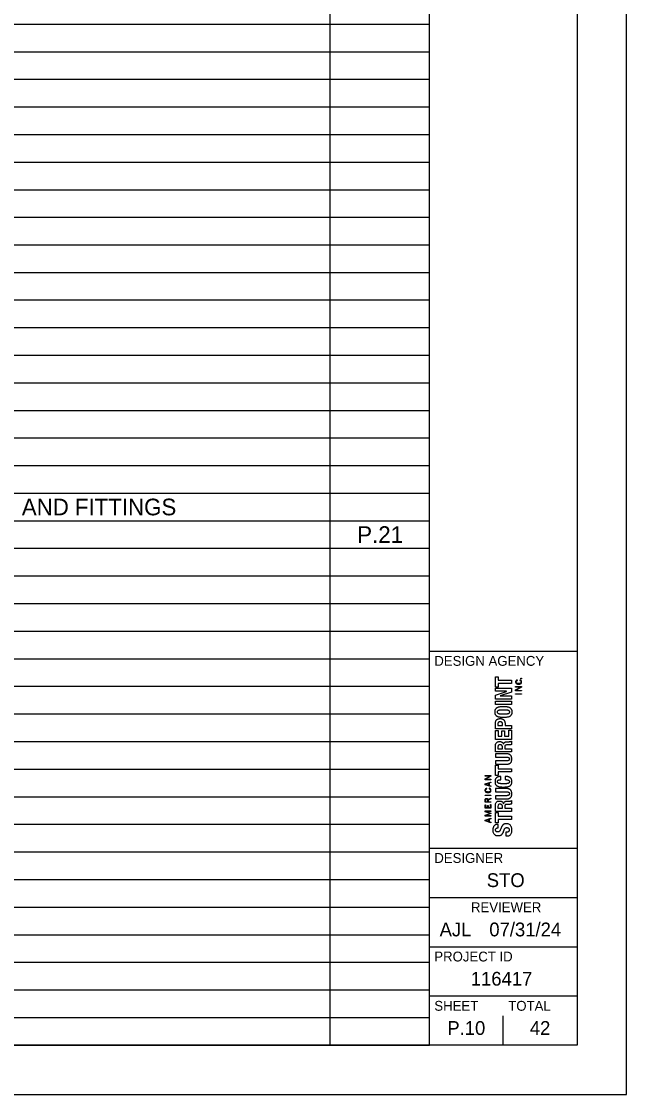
# Model space of a CAD drawing. Extents: x 0 to 34, y 0 to 22.
# Drawn here: x 27.86 to 34, y 0 to 10.89 of the extents above; entities that cross this region are included whole.
import ezdxf

# ---------------------------------------------------------------- set-up
doc = ezdxf.new("R2010")
doc.units = 0
for name, color, linetype in [('SH_Border', 7, 'Continuous'), ('SH_Cut_Line', 7, 'Continuous'), ('SH_Data', 7, 'Continuous')]:
    doc.layers.add(name, color=color, linetype=linetype)

msp = doc.modelspace()

# ---------------------------------------------------------------- linework, layer by layer
at = {"layer": 'SH_Border'}
for p, q in [((32, 0.5), (32, 21.5)), ((32, 4.5), (33.5, 4.5)), ((32, 2.5), (33.5, 2.5)), ((32, 2), (33.5, 2)), ((32, 1.5), (33.5, 1.5)), ((32, 1), (33.5, 1))]:
    msp.add_line(p, q, dxfattribs=at)
msp.add_lwpolyline([(1.5, 21.5), (33.5, 21.5), (33.5, 0.5), (1.5, 0.5)], close=True, dxfattribs=at)
at = {"layer": 'SH_Cut_Line'}
msp.add_lwpolyline([(0, 0), (34, 0), (34, 22), (0, 22)], close=True, dxfattribs=at)
at = {"layer": 'SH_Data'}
for p, q in [((30.995, 0.502), (30.995, 21.5)), ((32, 0.502), (32, 21.5)), ((1.5, 10.861), (32, 10.861)), ((1.5, 10.581), (32, 10.581)), ((1.5, 10.301), (32, 10.301)), ((1.5, 10.021), (32, 10.021)), ((1.5, 9.741), (32, 9.741)), ((1.5, 9.461), (32, 9.461)), ((1.5, 9.181), (32, 9.181)), ((1.5, 8.901), (32, 8.901)), ((1.5, 8.621), (32, 8.621)), ((1.5, 8.341), (32, 8.341)), ((1.5, 8.062), (32, 8.062)), ((1.5, 7.782), (32, 7.782)), ((1.5, 7.502), (32, 7.502)), ((1.5, 7.222), (32, 7.222)), ((1.5, 6.942), (32, 6.942)), ((1.5, 6.662), (32, 6.662)), ((1.5, 6.382), (32, 6.382)), ((1.5, 6.102), (32, 6.102)), ((1.5, 5.822), (32, 5.822)), ((1.5, 5.542), (32, 5.542)), ((1.5, 5.262), (32, 5.262)), ((1.5, 4.982), (32, 4.982)), ((1.5, 4.702), (32, 4.702)), ((1.5, 4.422), (32, 4.422)), ((1.5, 4.142), (32, 4.142)), ((1.5, 3.862), (32, 3.862)), ((1.5, 3.582), (32, 3.582)), ((32.75, 3.5), (32.75, 3.5)), ((32.75, 3.5), (32.75, 3.5)), ((1.5, 3.302), (32, 3.302)), ((1.5, 3.022), (32, 3.022)), ((1.5, 2.742), (32, 2.742)), ((1.5, 2.462), (32, 2.462)), ((1.5, 2.182), (32, 2.182)), ((1.5, 1.902), (32, 1.902)), ((1.5, 1.622), (32, 1.622)), ((1.5, 1.342), (32, 1.342)), ((1.5, 1.062), (32, 1.062)), ((1.5, 0.782), (32, 0.782)), ((32.75, 0.5), (32.75, 0.8)), ((32.375, 0.675), (32.375, 0.675)), ((1.5, 0.502), (32, 0.502))]:
    msp.add_line(p, q, dxfattribs=at)
for points in [[(32.67, 4.239), (32.697, 4.239), (32.697, 4.204), (32.833, 4.204), (32.833, 4.171), (32.697, 4.171), (32.697, 4.135), (32.67, 4.135), (32.67, 4.239)], [(32.875, 4.096), (32.875, 4.105), (32.925, 4.134), (32.925, 4.134), (32.875, 4.134), (32.875, 4.139), (32.935, 4.139), (32.935, 4.134), (32.88, 4.102), (32.88, 4.101), (32.935, 4.101), (32.935, 4.096), (32.875, 4.096)], [(32.935, 4.218), (32.927, 4.218), (32.927, 4.225), (32.935, 4.225), (32.935, 4.218)], [(32.67, 4.051), (32.781, 4.091), (32.781, 4.092), (32.67, 4.092), (32.67, 4.122), (32.833, 4.122), (32.833, 4.084), (32.719, 4.044), (32.719, 4.044), (32.833, 4.044), (32.833, 4.013), (32.67, 4.013), (32.67, 4.051)], [(32.875, 4.061), (32.875, 4.067), (32.935, 4.067), (32.935, 4.061), (32.875, 4.061)], [(32.833, 3.957), (32.67, 3.957), (32.67, 3.99), (32.833, 3.99), (32.833, 3.957)], [(32.833, 3.712), (32.67, 3.712), (32.67, 3.769)], [(32.694, 3.744), (32.743, 3.744), (32.743, 3.759)], [(32.694, 3.758), (32.694, 3.744)], [(32.768, 3.762), (32.768, 3.744), (32.833, 3.744), (32.833, 3.712)], [(32.67, 3.694), (32.697, 3.694), (32.697, 3.635), (32.735, 3.635), (32.735, 3.69), (32.762, 3.69), (32.762, 3.635), (32.806, 3.635), (32.806, 3.696), (32.833, 3.696), (32.833, 3.603), (32.67, 3.603), (32.67, 3.694)], [(32.833, 3.476), (32.67, 3.476), (32.67, 3.537)], [(32.694, 3.525), (32.694, 3.509)], [(32.694, 3.509), (32.741, 3.509), (32.741, 3.523)], [(32.752, 3.554), (32.752, 3.554)], [(32.764, 3.527), (32.764, 3.509), (32.833, 3.509), (32.833, 3.476)], [(32.816, 3.548), (32.784, 3.547)], [(32.832, 3.587), (32.833, 3.587), (32.833, 3.552)], [(32.67, 3.341), (32.697, 3.341), (32.697, 3.305), (32.833, 3.305), (32.833, 3.273), (32.697, 3.273), (32.697, 3.237), (32.67, 3.237), (32.67, 3.341)], [(32.565, 3.194), (32.565, 3.203), (32.615, 3.231), (32.615, 3.231), (32.565, 3.231), (32.565, 3.237), (32.625, 3.237), (32.625, 3.231), (32.569, 3.199), (32.569, 3.199), (32.625, 3.199), (32.625, 3.194), (32.565, 3.194)], [(32.625, 3.125), (32.565, 3.144), (32.565, 3.152), (32.625, 3.171), (32.625, 3.165), (32.605, 3.159), (32.605, 3.137), (32.625, 3.131), (32.625, 3.125)], [(32.601, 3.138), (32.601, 3.158), (32.569, 3.148), (32.569, 3.148), (32.601, 3.138)], [(32.565, 3.034), (32.565, 3.039), (32.625, 3.039), (32.625, 3.034), (32.565, 3.034)], [(32.596, 2.992), (32.625, 3.006), (32.625, 3), (32.597, 2.987), (32.597, 2.971), (32.625, 2.971), (32.625, 2.966), (32.565, 2.966), (32.565, 2.986)], [(32.625, 2.907), (32.565, 2.907), (32.565, 2.941), (32.569, 2.941), (32.569, 2.913), (32.591, 2.913), (32.591, 2.933), (32.596, 2.933), (32.596, 2.913), (32.62, 2.913), (32.62, 2.943), (32.625, 2.943), (32.625, 2.907)], [(32.569, 2.971), (32.593, 2.971), (32.593, 2.986)], [(32.569, 2.986), (32.569, 2.971)], [(32.752, 2.951), (32.752, 2.951)], [(32.816, 2.944), (32.784, 2.944)], [(32.832, 2.984), (32.833, 2.984), (32.833, 2.949)], [(32.625, 2.826), (32.565, 2.826), (32.565, 2.836), (32.615, 2.852), (32.615, 2.853), (32.565, 2.869), (32.565, 2.879), (32.625, 2.879), (32.625, 2.873), (32.569, 2.873), (32.569, 2.873), (32.625, 2.855), (32.625, 2.85), (32.569, 2.832), (32.569, 2.832), (32.625, 2.832), (32.625, 2.826)], [(32.833, 2.873), (32.67, 2.873), (32.67, 2.934)], [(32.67, 2.86), (32.697, 2.86), (32.697, 2.824), (32.833, 2.824), (32.833, 2.791), (32.697, 2.791), (32.697, 2.756), (32.67, 2.756), (32.67, 2.86)], [(32.694, 2.922), (32.694, 2.906)], [(32.694, 2.906), (32.741, 2.906), (32.741, 2.92)], [(32.764, 2.924), (32.764, 2.906), (32.833, 2.906), (32.833, 2.873)], [(32.625, 2.758), (32.565, 2.777), (32.565, 2.785), (32.625, 2.804), (32.625, 2.798), (32.605, 2.792), (32.605, 2.769), (32.625, 2.763), (32.625, 2.758)], [(32.601, 2.771), (32.601, 2.791), (32.569, 2.781), (32.569, 2.781), (32.601, 2.771)]]:
    msp.add_lwpolyline(points, dxfattribs=at)
for points in [[(32.893, 4.201), (32.889, 4.199), (32.885, 4.197), (32.883, 4.195), (32.88, 4.193), (32.879, 4.19), (32.879, 4.186), (32.879, 4.183), (32.88, 4.181), (32.881, 4.178), (32.882, 4.176), (32.884, 4.175), (32.887, 4.173), (32.889, 4.172), (32.892, 4.171), (32.895, 4.17), (32.898, 4.169), (32.902, 4.169), (32.905, 4.169), (32.909, 4.169), (32.912, 4.169), (32.915, 4.17), (32.919, 4.171), (32.921, 4.172), (32.924, 4.173), (32.926, 4.175), (32.928, 4.176), (32.929, 4.179), (32.931, 4.181), (32.931, 4.184), (32.931, 4.187), (32.931, 4.189), (32.931, 4.191), (32.93, 4.193), (32.929, 4.194), (32.928, 4.196), (32.927, 4.197), (32.926, 4.198), (32.924, 4.199), (32.922, 4.2), (32.921, 4.2), (32.919, 4.201), (32.917, 4.202), (32.917, 4.202), (32.918, 4.207), (32.918, 4.207), (32.92, 4.206), (32.923, 4.205), (32.925, 4.204), (32.927, 4.203), (32.929, 4.202), (32.931, 4.2), (32.932, 4.199), (32.934, 4.197), (32.934, 4.195), (32.935, 4.192), (32.936, 4.19), (32.936, 4.187), (32.936, 4.183), (32.935, 4.18), (32.934, 4.177), (32.932, 4.174), (32.93, 4.172), (32.927, 4.17), (32.925, 4.168), (32.921, 4.166), (32.918, 4.165), (32.914, 4.164), (32.91, 4.164), (32.905, 4.164), (32.901, 4.164), (32.896, 4.164), (32.893, 4.165), (32.889, 4.166), (32.886, 4.168), (32.883, 4.17), (32.88, 4.172), (32.878, 4.174), (32.877, 4.177), (32.875, 4.18), (32.875, 4.183), (32.875, 4.187), (32.875, 4.189), (32.875, 4.192), (32.876, 4.194), (32.877, 4.196), (32.878, 4.198), (32.88, 4.199), (32.881, 4.201), (32.883, 4.202), (32.885, 4.203), (32.887, 4.204), (32.889, 4.205), (32.892, 4.206), (32.892, 4.206), (32.893, 4.201), (32.893, 4.201)], [(32.751, 3.826), (32.739, 3.826), (32.727, 3.826), (32.717, 3.828), (32.706, 3.829), (32.697, 3.831), (32.69, 3.835), (32.682, 3.839), (32.677, 3.845), (32.672, 3.852), (32.668, 3.859), (32.666, 3.869), (32.666, 3.882), (32.666, 3.894), (32.668, 3.904), (32.672, 3.911), (32.677, 3.918), (32.682, 3.924), (32.69, 3.928), (32.697, 3.932), (32.706, 3.934), (32.717, 3.936), (32.727, 3.937), (32.739, 3.937), (32.751, 3.937), (32.758, 3.937), (32.764, 3.937), (32.771, 3.937)], [(32.771, 3.937), (32.776, 3.936), (32.781, 3.936), (32.785, 3.936), (32.796, 3.934), (32.805, 3.932), (32.812, 3.928), (32.82, 3.924), (32.825, 3.918), (32.83, 3.911), (32.834, 3.904), (32.836, 3.894), (32.836, 3.882), (32.836, 3.869), (32.834, 3.859), (32.83, 3.852), (32.825, 3.845), (32.82, 3.839), (32.812, 3.835), (32.805, 3.831), (32.796, 3.829), (32.785, 3.828), (32.775, 3.826), (32.763, 3.826), (32.751, 3.826)], [(32.67, 3.769), (32.67, 3.777), (32.671, 3.784), (32.674, 3.79), (32.677, 3.796), (32.68, 3.8), (32.685, 3.804), (32.689, 3.807), (32.695, 3.81), (32.701, 3.812), (32.706, 3.813), (32.712, 3.814), (32.719, 3.814), (32.727, 3.814), (32.734, 3.813), (32.741, 3.81), (32.747, 3.808), (32.752, 3.804), (32.756, 3.8), (32.76, 3.795), (32.763, 3.79), (32.765, 3.783), (32.767, 3.777), (32.768, 3.77), (32.768, 3.762)], [(32.751, 3.859), (32.762, 3.859), (32.771, 3.859), (32.779, 3.859), (32.787, 3.86), (32.793, 3.861), (32.798, 3.863), (32.803, 3.864), (32.806, 3.867), (32.808, 3.87), (32.81, 3.873), (32.812, 3.877), (32.812, 3.882), (32.812, 3.886), (32.81, 3.89), (32.808, 3.893), (32.806, 3.896), (32.803, 3.899), (32.798, 3.9), (32.793, 3.902), (32.787, 3.903), (32.779, 3.904), (32.771, 3.904), (32.762, 3.904), (32.751, 3.904), (32.74, 3.904), (32.731, 3.904), (32.723, 3.904), (32.716, 3.903), (32.709, 3.902), (32.704, 3.9), (32.7, 3.899), (32.696, 3.896), (32.694, 3.893), (32.692, 3.89), (32.691, 3.886), (32.691, 3.882), (32.691, 3.877), (32.692, 3.873), (32.694, 3.87), (32.696, 3.867), (32.7, 3.864), (32.704, 3.863), (32.709, 3.861), (32.716, 3.86), (32.723, 3.859), (32.731, 3.859), (32.74, 3.859), (32.751, 3.859)], [(32.743, 3.759), (32.743, 3.766), (32.741, 3.771), (32.737, 3.775), (32.733, 3.779), (32.727, 3.781), (32.719, 3.781), (32.711, 3.781), (32.705, 3.779), (32.7, 3.776), (32.696, 3.772), (32.694, 3.766), (32.694, 3.758)], [(32.67, 3.537), (32.67, 3.551), (32.673, 3.562), (32.68, 3.569), (32.687, 3.577), (32.698, 3.581), (32.712, 3.581), (32.723, 3.581), (32.732, 3.579), (32.739, 3.574), (32.745, 3.57), (32.75, 3.563), (32.752, 3.554)], [(32.741, 3.523), (32.741, 3.531), (32.739, 3.537), (32.735, 3.542), (32.732, 3.546), (32.725, 3.548), (32.717, 3.548), (32.702, 3.548), (32.694, 3.54), (32.694, 3.525)], [(32.752, 3.554), (32.753, 3.559), (32.755, 3.564), (32.757, 3.567), (32.759, 3.571), (32.762, 3.573), (32.766, 3.575), (32.769, 3.577), (32.774, 3.578), (32.78, 3.579), (32.786, 3.58), (32.794, 3.58), (32.802, 3.58), (32.811, 3.58), (32.818, 3.581), (32.822, 3.582), (32.827, 3.582), (32.83, 3.584), (32.832, 3.587)], [(32.784, 3.547), (32.778, 3.546), (32.773, 3.545), (32.769, 3.542), (32.766, 3.539), (32.764, 3.534), (32.764, 3.527)], [(32.833, 3.552), (32.831, 3.55), (32.828, 3.549), (32.825, 3.549), (32.822, 3.548), (32.819, 3.548), (32.816, 3.548)], [(32.67, 3.385), (32.67, 3.385), (32.783, 3.385), (32.783, 3.385), (32.787, 3.385), (32.791, 3.385), (32.795, 3.386), (32.798, 3.387), (32.801, 3.388), (32.803, 3.389), (32.806, 3.39), (32.808, 3.392), (32.809, 3.395), (32.811, 3.397), (32.812, 3.401), (32.812, 3.404), (32.812, 3.408), (32.811, 3.411), (32.809, 3.414), (32.808, 3.417), (32.806, 3.418), (32.803, 3.42), (32.801, 3.421), (32.798, 3.422), (32.795, 3.423), (32.791, 3.423), (32.787, 3.424), (32.783, 3.424), (32.783, 3.424), (32.67, 3.424), (32.67, 3.424), (32.67, 3.424), (32.67, 3.457), (32.67, 3.457), (32.67, 3.457), (32.783, 3.457), (32.783, 3.457), (32.794, 3.457), (32.802, 3.455), (32.809, 3.452), (32.816, 3.449), (32.821, 3.445), (32.825, 3.441), (32.829, 3.436), (32.832, 3.43), (32.834, 3.424), (32.835, 3.418), (32.836, 3.411), (32.836, 3.404), (32.836, 3.398), (32.835, 3.391), (32.834, 3.385), (32.833, 3.379), (32.83, 3.373), (32.826, 3.368), (32.822, 3.363), (32.817, 3.36), (32.81, 3.357), (32.803, 3.354), (32.794, 3.352), (32.783, 3.352), (32.783, 3.352), (32.67, 3.352), (32.67, 3.352), (32.67, 3.352), (32.67, 3.385), (32.67, 3.385)], [(32.725, 3.193), (32.713, 3.193), (32.704, 3.192), (32.699, 3.189), (32.693, 3.186), (32.691, 3.181), (32.691, 3.174), (32.691, 3.17), (32.692, 3.166), (32.694, 3.163), (32.696, 3.161), (32.7, 3.159), (32.705, 3.157), (32.71, 3.156), (32.716, 3.155), (32.724, 3.154), (32.732, 3.153), (32.742, 3.153), (32.753, 3.153), (32.766, 3.153), (32.776, 3.153), (32.783, 3.154), (32.791, 3.155), (32.797, 3.156), (32.801, 3.158), (32.805, 3.16), (32.808, 3.162), (32.809, 3.165), (32.811, 3.168), (32.812, 3.171), (32.812, 3.174), (32.812, 3.177), (32.811, 3.18), (32.81, 3.182), (32.809, 3.185), (32.807, 3.187), (32.804, 3.189), (32.801, 3.191), (32.797, 3.192), (32.792, 3.193), (32.786, 3.194), (32.779, 3.195), (32.77, 3.195), (32.77, 3.195), (32.77, 3.228), (32.77, 3.228), (32.779, 3.228), (32.787, 3.227), (32.795, 3.226), (32.803, 3.224), (32.81, 3.222), (32.816, 3.218), (32.822, 3.214), (32.827, 3.209), (32.831, 3.202), (32.834, 3.196), (32.836, 3.187), (32.836, 3.176), (32.836, 3.163), (32.834, 3.154), (32.83, 3.146), (32.825, 3.139), (32.82, 3.133), (32.812, 3.129), (32.805, 3.126), (32.796, 3.123), (32.785, 3.122), (32.775, 3.121), (32.763, 3.12), (32.751, 3.12), (32.739, 3.12), (32.727, 3.121), (32.717, 3.122), (32.706, 3.123), (32.697, 3.126), (32.69, 3.129), (32.682, 3.133), (32.677, 3.139), (32.672, 3.146), (32.668, 3.154), (32.666, 3.163), (32.666, 3.176), (32.666, 3.188), (32.668, 3.197), (32.672, 3.204), (32.676, 3.21), (32.681, 3.215), (32.687, 3.219), (32.692, 3.222), (32.699, 3.224), (32.706, 3.225), (32.712, 3.226), (32.719, 3.226), (32.725, 3.226), (32.725, 3.226), (32.725, 3.193), (32.725, 3.193)], [(32.582, 3.101), (32.578, 3.1), (32.575, 3.098), (32.572, 3.095), (32.57, 3.093), (32.569, 3.09), (32.569, 3.086), (32.569, 3.083), (32.569, 3.081), (32.571, 3.079), (32.572, 3.077), (32.574, 3.075), (32.576, 3.074), (32.579, 3.072), (32.581, 3.071), (32.585, 3.07), (32.588, 3.07), (32.591, 3.069), (32.595, 3.069), (32.598, 3.069), (32.602, 3.07), (32.605, 3.07), (32.608, 3.071), (32.611, 3.072), (32.613, 3.074), (32.616, 3.075), (32.618, 3.077), (32.619, 3.079), (32.62, 3.081), (32.621, 3.084), (32.621, 3.087), (32.621, 3.089), (32.62, 3.091), (32.62, 3.093), (32.619, 3.095), (32.618, 3.096), (32.617, 3.097), (32.615, 3.098), (32.614, 3.099), (32.612, 3.1), (32.61, 3.101), (32.608, 3.102), (32.606, 3.102), (32.606, 3.102), (32.607, 3.107), (32.607, 3.107), (32.61, 3.107), (32.612, 3.106), (32.615, 3.105), (32.617, 3.104), (32.619, 3.102), (32.62, 3.101), (32.622, 3.099), (32.623, 3.097), (32.624, 3.095), (32.625, 3.093), (32.625, 3.09), (32.625, 3.087), (32.625, 3.083), (32.625, 3.08), (32.623, 3.077), (32.622, 3.074), (32.62, 3.072), (32.617, 3.07), (32.614, 3.068), (32.611, 3.067), (32.607, 3.066), (32.604, 3.065), (32.599, 3.064), (32.595, 3.064), (32.59, 3.064), (32.586, 3.065), (32.582, 3.066), (32.579, 3.067), (32.575, 3.068), (32.573, 3.07), (32.57, 3.072), (32.568, 3.074), (32.566, 3.077), (32.565, 3.08), (32.564, 3.083), (32.564, 3.087), (32.564, 3.09), (32.565, 3.092), (32.566, 3.094), (32.566, 3.096), (32.568, 3.098), (32.569, 3.099), (32.571, 3.101), (32.572, 3.102), (32.575, 3.103), (32.577, 3.104), (32.579, 3.105), (32.581, 3.106), (32.581, 3.106), (32.582, 3.101), (32.582, 3.101)], [(32.67, 3.032), (32.67, 3.032), (32.783, 3.032), (32.783, 3.032), (32.787, 3.032), (32.791, 3.033), (32.795, 3.033), (32.798, 3.034), (32.801, 3.035), (32.803, 3.036), (32.806, 3.038), (32.808, 3.04), (32.809, 3.042), (32.811, 3.045), (32.812, 3.048), (32.812, 3.052), (32.812, 3.056), (32.811, 3.059), (32.809, 3.061), (32.808, 3.064), (32.806, 3.066), (32.803, 3.067), (32.801, 3.069), (32.798, 3.07), (32.795, 3.07), (32.791, 3.071), (32.787, 3.071), (32.783, 3.071), (32.783, 3.071), (32.67, 3.071), (32.67, 3.071), (32.67, 3.071), (32.67, 3.104), (32.67, 3.104), (32.67, 3.104), (32.783, 3.104), (32.783, 3.104), (32.794, 3.104), (32.802, 3.102), (32.809, 3.1), (32.816, 3.097), (32.821, 3.093), (32.825, 3.088), (32.829, 3.083), (32.832, 3.077), (32.834, 3.071), (32.835, 3.065), (32.836, 3.058), (32.836, 3.052), (32.836, 3.045), (32.835, 3.039), (32.834, 3.032), (32.833, 3.026), (32.83, 3.021), (32.826, 3.016), (32.822, 3.011), (32.817, 3.007), (32.81, 3.004), (32.803, 3.001), (32.794, 3), (32.783, 3), (32.783, 3), (32.67, 3), (32.67, 3), (32.67, 3), (32.67, 3.032), (32.67, 3.032)], [(32.565, 2.986), (32.565, 2.992), (32.566, 2.996), (32.569, 2.999), (32.572, 3.003), (32.576, 3.004), (32.581, 3.004), (32.585, 3.004), (32.588, 3.003), (32.591, 3.001), (32.593, 2.999), (32.595, 2.996), (32.596, 2.992)], [(32.593, 2.986), (32.593, 2.99), (32.592, 2.993), (32.59, 2.995), (32.588, 2.997), (32.585, 2.999), (32.581, 2.999), (32.577, 2.999), (32.575, 2.998), (32.573, 2.995), (32.57, 2.993), (32.569, 2.99), (32.569, 2.986)], [(32.67, 2.934), (32.67, 2.948), (32.673, 2.958), (32.68, 2.966), (32.687, 2.974), (32.698, 2.978), (32.712, 2.978), (32.723, 2.978), (32.732, 2.975), (32.739, 2.971), (32.745, 2.967), (32.75, 2.96), (32.752, 2.951)], [(32.741, 2.92), (32.741, 2.928), (32.739, 2.934), (32.735, 2.938), (32.732, 2.943), (32.725, 2.945), (32.717, 2.945), (32.702, 2.945), (32.694, 2.937), (32.694, 2.922)], [(32.752, 2.951), (32.753, 2.956), (32.755, 2.961), (32.757, 2.964), (32.759, 2.967), (32.762, 2.97), (32.766, 2.972), (32.769, 2.974), (32.774, 2.975), (32.78, 2.976), (32.786, 2.976), (32.794, 2.977), (32.802, 2.977), (32.811, 2.977), (32.818, 2.978), (32.822, 2.978), (32.827, 2.979), (32.83, 2.981), (32.832, 2.984)], [(32.784, 2.944), (32.778, 2.943), (32.773, 2.942), (32.769, 2.939), (32.766, 2.936), (32.764, 2.931), (32.764, 2.924)], [(32.833, 2.949), (32.831, 2.947), (32.828, 2.946), (32.825, 2.945), (32.822, 2.945), (32.819, 2.945), (32.816, 2.944)], [(32.775, 2.661), (32.775, 2.661), (32.781, 2.661), (32.781, 2.661), (32.785, 2.661), (32.789, 2.662), (32.793, 2.662), (32.796, 2.663), (32.799, 2.664), (32.801, 2.666), (32.804, 2.668), (32.806, 2.671), (32.807, 2.674), (32.809, 2.677), (32.809, 2.681), (32.809, 2.686), (32.809, 2.692), (32.807, 2.697), (32.804, 2.701), (32.8, 2.706), (32.794, 2.708), (32.786, 2.708), (32.782, 2.708), (32.779, 2.708), (32.776, 2.707), (32.773, 2.705), (32.77, 2.704), (32.767, 2.701), (32.765, 2.698), (32.763, 2.695), (32.761, 2.691), (32.759, 2.687), (32.757, 2.681), (32.755, 2.675), (32.752, 2.667), (32.749, 2.66), (32.745, 2.654), (32.742, 2.647), (32.738, 2.642), (32.734, 2.638), (32.73, 2.634), (32.725, 2.631), (32.719, 2.629), (32.713, 2.628), (32.706, 2.627), (32.699, 2.627), (32.68, 2.627), (32.667, 2.632), (32.658, 2.642), (32.649, 2.652), (32.644, 2.666), (32.644, 2.684), (32.644, 2.692), (32.645, 2.7), (32.647, 2.707), (32.649, 2.714), (32.651, 2.72), (32.656, 2.725), (32.66, 2.73), (32.665, 2.734), (32.671, 2.737), (32.677, 2.74), (32.685, 2.741), (32.694, 2.741), (32.694, 2.741), (32.699, 2.741), (32.699, 2.741), (32.699, 2.741), (32.699, 2.705), (32.699, 2.705), (32.69, 2.705), (32.683, 2.704), (32.679, 2.701), (32.674, 2.697), (32.671, 2.692), (32.671, 2.685), (32.671, 2.681), (32.672, 2.678), (32.673, 2.675), (32.675, 2.672), (32.676, 2.67), (32.678, 2.668), (32.68, 2.667), (32.682, 2.665), (32.685, 2.665), (32.688, 2.664), (32.69, 2.664), (32.693, 2.664), (32.699, 2.664), (32.704, 2.665), (32.707, 2.668), (32.711, 2.67), (32.715, 2.675), (32.718, 2.683), (32.718, 2.683), (32.731, 2.712), (32.731, 2.712), (32.734, 2.719), (32.737, 2.725), (32.74, 2.729), (32.744, 2.734), (32.747, 2.737), (32.751, 2.74), (32.755, 2.743), (32.76, 2.745), (32.764, 2.746), (32.769, 2.747), (32.774, 2.747), (32.78, 2.747), (32.799, 2.747), (32.814, 2.742), (32.823, 2.73), (32.832, 2.719), (32.837, 2.703), (32.837, 2.683), (32.837, 2.662), (32.832, 2.647), (32.823, 2.638), (32.813, 2.628), (32.8, 2.624), (32.783, 2.624), (32.783, 2.624), (32.775, 2.624), (32.775, 2.624), (32.775, 2.624), (32.775, 2.661), (32.775, 2.661)]]:
    msp.add_open_spline(points, degree=3, dxfattribs=at)

# ---------------------------------------------------------------- texts
for s, height, p in [(' AND', 0.1689, (27.803, 5.877)), (' FITTINGS', 0.1689, (28.341, 5.877)), ('P.21', 0.1689, (31.268, 5.597)), ('DESIGN AGENCY', 0.1, (32.05, 4.35)), ('DESIGNER', 0.1, (32.05, 2.35)), ('STO', 0.14, (32.582, 2.105)), ('REVIEWER', 0.1, (32.422, 1.85)), ('AJL', 0.14, (32.104, 1.605)), ('07/31/24', 0.14, (32.608, 1.605)), ('PROJECT ID', 0.1, (32.05, 1.35)), ('116417', 0.14, (32.42, 1.105)), ('SHEET', 0.1, (32.05, 0.85)), ('TOTAL', 0.1, (32.8, 0.85)), ('P.10', 0.14, (32.182, 0.605)), ('42', 0.14, (33.019, 0.605))]:
    msp.add_text(s, height=height, dxfattribs=at).set_placement(p)

doc.saveas('drawing.dxf')
